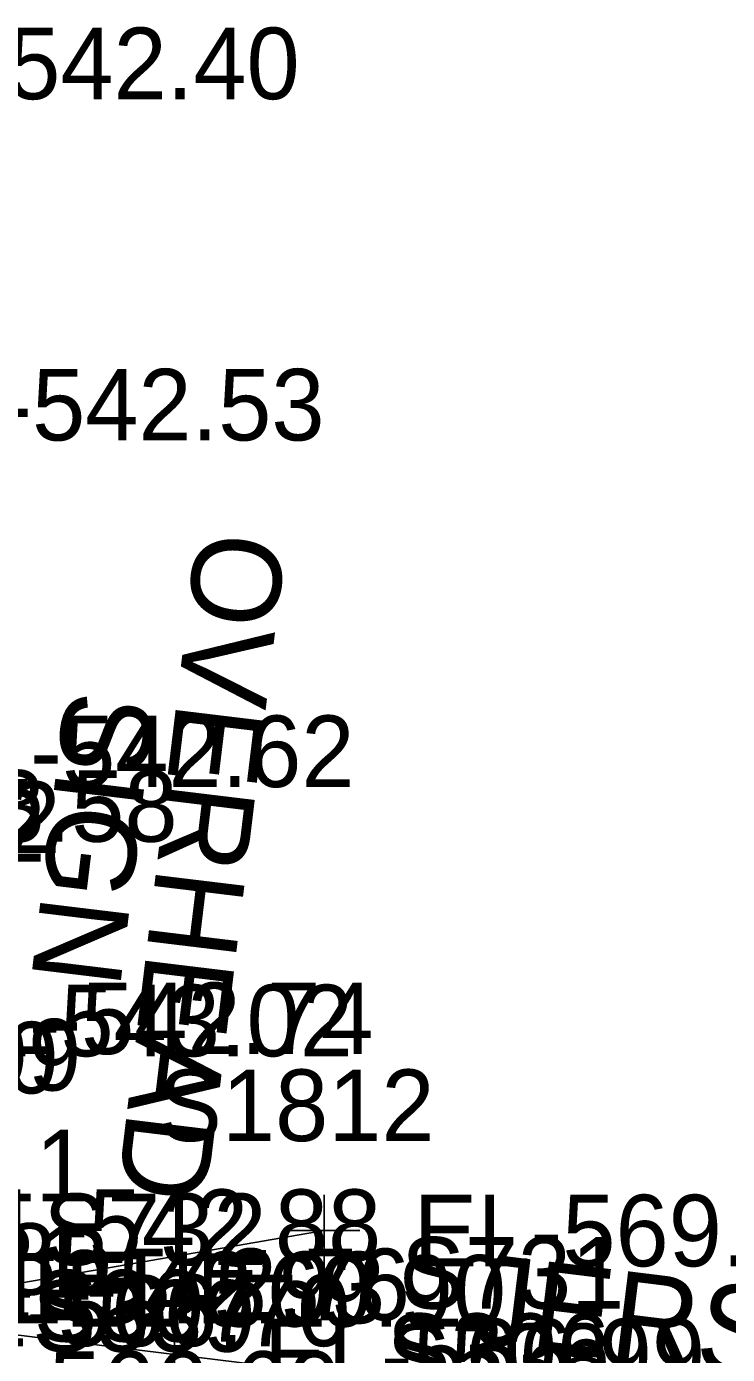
# Model space of a CAD drawing. Extents: x 1724534 to 1727318, y 657156 to 660047.
# Drawn here: x 1725579.1 to 1725618.3, y 658642.3 to 658716.6 of the extents above; entities that cross this region are included whole.
import ezdxf

# ---------------------------------------------------------------- set-up
doc = ezdxf.new("R2010")
doc.units = 0
for name, color, linetype in [('SURVEY - DTM - Breaklines - Points - Elevations', 7, 'Continuous'), ('SURVEY - DTM - Breaklines - Points - Numbers', 7, 'Continuous'), ('SURVEY - ROADSIDE BARRIERS - Points - Elevations', 7, 'Continuous'), ('SURVEY - ROADSIDE BARRIERS - Points - Locators', 7, 'Continuous'), ('SURVEY - ROADSIDE BARRIERS - Points - Numbers', 7, 'Continuous'), ('SURVEY - ROADSIDE BARRIERS with Text', 7, 'Continuous'), ('SURVEY - TRAFFIC CONTROL - Signs - Points - Elevations', 7, 'Continuous'), ('SURVEY - TRAFFIC CONTROL - Signs - Points - Locators', 7, 'Continuous'), ('SURVEY - TRAFFIC CONTROL - Signs - Points - Numbers', 7, 'Continuous'), ('SURVEY - TRAFFIC CONTROL - Signs and Devices with Text', 7, 'Continuous'), ('SURVEY - TRANSPORTATION - Features - Points - Elevations', 7, 'Continuous'), ('SURVEY - TRANSPORTATION - Features - Points - Numbers', 7, 'Continuous'), ('SURVEY - UTILITIES - Poles and Miscellaneous - Points - Elevations', 7, 'Continuous')]:
    doc.layers.add(name, color=color, linetype=linetype)

msp = doc.modelspace()

# ---------------------------------------------------------------- linework, layer by layer
at = {"layer": 'SURVEY - ROADSIDE BARRIERS - Points - Locators'}
msp.add_line((1725587.342, 658644.328), (1725587.342, 658640.328), dxfattribs=at)
at = {"layer": 'SURVEY - ROADSIDE BARRIERS with Text'}
msp.add_lwpolyline([(1725749.441, 658623.208), (1725747.683, 658622.944), (1725746.171, 658622.954), (1725726.297, 658625.19), (1725706.432, 658627.625), (1725686.585, 658630.082), (1725666.736, 658632.525), (1725646.891, 658635.007), (1725627.042, 658637.458), (1725607.192, 658639.897), (1725587.342, 658642.328), (1725567.496, 658644.799), (1725547.649, 658647.261), (1725530.293, 658649.414), (1725527.821, 658649.879), (1725526.283, 658650.157), (1725524.746, 658650.804)], dxfattribs=at)
at = {"layer": 'SURVEY - TRAFFIC CONTROL - Signs - Points - Locators'}
for p, q in [((1725595.715, 658651.263), (1725595.715, 658647.263)), ((1725597.715, 658649.263), (1725593.715, 658649.263))]:
    msp.add_line(p, q, dxfattribs=at)
at = {"layer": 'SURVEY - TRAFFIC CONTROL - Signs and Devices with Text'}
msp.add_line((1725576.204, 658645.894), (1725595.715, 658649.263), dxfattribs=at)

# ---------------------------------------------------------------- texts
at = {"layer": 'SURVEY - DTM - Breaklines - Points - Elevations'}
for s, p in [('EL-545.12', (1725555.443, 658669.884)), ('EL-543.02', (1725572.64, 658659.002)), ('EL-544.99', (1725557.445, 658657.088)), ('EL-556.70', (1725556.15, 658656.927)), ('EL-542.88', (1725574.221, 658647.558)), ('EL-558.21', (1725557.828, 658645.519)), ('EL-545.85', (1725559.029, 658645.668)), ('EL-542.93', (1725574.441, 658644.08)), ('EL-566.60', (1725571.963, 658638.515))]:
    msp.add_text(s, height=4, dxfattribs=at).set_placement(p)
at = {"layer": 'SURVEY - DTM - Breaklines - Points - Numbers'}
for s, p in [('S307', (1725579.474, 658643.059)), ('S306', (1725599.215, 658640.629))]:
    msp.add_text(s, height=4, dxfattribs=at).set_placement(p)
at = {"layer": 'SURVEY - ROADSIDE BARRIERS - Points - Elevations'}
for s, p in [('EL-566.70', (1725572.496, 658642.799)), ('EL-566.99', (1725592.342, 658640.328))]:
    msp.add_text(s, height=4, dxfattribs=at).set_placement(p)
at = {"layer": 'SURVEY - ROADSIDE BARRIERS - Points - Numbers'}
for s, p in [('S732', (1725580.006, 658647.328)), ('S731', (1725600.014, 658644.897))]:
    msp.add_text(s, height=4, dxfattribs=at).set_placement(p)
at = {"layer": 'SURVEY - ROADSIDE BARRIERS with Text'}
msp.add_text('JERSEY BARRIER WALL/BRIDGE', height=5, rotation=352.99509, dxfattribs=at).set_placement((1725603.82, 658643.041))
at = {"layer": 'SURVEY - TRAFFIC CONTROL - Signs - Points - Elevations'}
for s, p in [('EL-569.86', (1725600.715, 658647.263)), ('EL-569.90', (1725581.204, 658643.894))]:
    msp.add_text(s, height=4, dxfattribs=at).set_placement(p)
at = {"layer": 'SURVEY - TRAFFIC CONTROL - Signs - Points - Numbers'}
for s, p in [('S1812', (1725586.427, 658654.263)), ('S1811', (1725567.074, 658650.894))]:
    msp.add_text(s, height=4, dxfattribs=at).set_placement(p)
at = {"layer": 'SURVEY - TRAFFIC CONTROL - Signs and Devices with Text'}
for s, p in [('OVERHEAD', (1725588.633, 658688.492)), ('SIGN', (1725581.285, 658679.551))]:
    msp.add_text(s, height=5, rotation=263.09355, dxfattribs=at).set_placement(p)
at = {"layer": 'SURVEY - TRANSPORTATION - Features - Points - Elevations'}
for s, p in [('EL-542.40', (1725569.662, 658712.496)), ('EL-542.53', (1725571.054, 658693.422)), ('EL-542.62', (1725572.732, 658674.049)), ('EL-542.74', (1725573.796, 658659.122)), ('EL-542.76', (1725575.831, 658644.253))]:
    msp.add_text(s, height=4, dxfattribs=at).set_placement(p)
at = {"layer": 'SURVEY - TRANSPORTATION - Features - Points - Numbers'}
for s, p in [('S539', (1725579.388, 658642.492)), ('S538', (1725599.208, 658640.062))]:
    msp.add_text(s, height=4, dxfattribs=at).set_placement(p)
at = {"layer": 'SURVEY - UTILITIES - Poles and Miscellaneous - Points - Elevations'}
for s, p in [('EL-545.02', (1725556.286, 658670.366)), ('EL-543.58', (1725562.832, 658670.993))]:
    msp.add_text(s, height=4, dxfattribs=at).set_placement(p)

doc.saveas('drawing.dxf')
